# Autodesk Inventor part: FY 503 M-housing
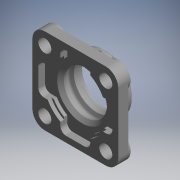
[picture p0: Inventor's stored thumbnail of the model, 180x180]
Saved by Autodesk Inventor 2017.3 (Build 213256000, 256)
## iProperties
Part Number: FY 503 M-housing
Material: Generic
Catalog Web Link: www.cadenas.de
Description: ayf_001hc_hh_hy-housing-Square flanged housings for Y-bearings
Vendor: SKF
Document SubType Name: Modeling
Designer: partserver
Manufacturer: SKF
Mass: 40.8035 g
Surface Area: 192.771 cm^2
Volume: 40.8035 cm^3
Density: 1 g/cm^3
Appearance: PSOLRGB-175-175-175
Category: PARTsolutions
Company: SKF
Title: FY 503 M-housing
Author: Cadenas PARTsolutions
Comments: Square flanged housings for Y-bearings
PSOL_IDENT_0: {$CADENAS_DATA\23d-libs\skf\bearings_units_and_housings\bearing_units\ball_bearing_units\y-units\y-b
PSOL_IDENT_1: earing_square_flanged_units_parts\ayf_001hc_hh_hy_housing.prj},196 {VTYP=3D},{NB=FY 503 M-housing},{
PSOL_IDENT_2: LINA=FY 503 M-housing},{NN=ayf_001hc_hh_hy-housing},{DATE=20.08.2020 13:45:19},{GEOMDATE=29.07.2020
PSOL_IDENT_3: 16:36:58},{VERSION=},{LINEID=8950},{WBVAR=COVER},{WBNUMERIC=}  {NB=FY 503 M-housing},{LINA=FY 503 M-
PSOL_IDENT_4: housing},{KT=DUMMY},{DESIGNATION=FY 503 M},{SS1=15.900},{T=32.900},{COVER=},{GN=1/4-28 SAE-LT},{D=40
PSOL_IDENT_5: .000},{DA=55.600},{DB1=50.000},{DB2=53.000},{DB=0.000},{A=26.000},{A1=11.000},{A2=17.000},{A3=3.200}
PSOL_IDENT_6: ,{A5=0.000},{J=54.000},{L=76.000},{N=11.500},{RG=1/4-28 UNF},{R1=19.000},{DN=6.500},{SWN=7.000},{J6=
PSOL_IDENT_7: 66.000},{J7=14.500},{N4=4.000},{EC=},{AEC=0.000},{DEC=0.000},{D1EC=0.000},{D2EC=0.000},{E=12},{DESIG
PSOL_IDENT_8: N=fy},{BRG=0.000},{ECPN=},{H4=MIN},{R2=MIN},{R3=MIN},{R4=MIN},{L1=MIN},{H5=MIN},{R5=MIN},{H6=MIN},{L
PSOL_IDENT_9: 2=MIN},{H7=MIN},{H8=MIN},{H9=MIN},{L3=MIN},{L4=MIN},{H10=MIN},{H11=MIN},{H12=MIN},{H13=MIN},{H14=MIN
PSOL_IDENT_10: },{R6=MIN},{L5=MIN},{H15=MIN},{H16=MIN},{SC=MIN}
NB: FY 503 M-housing
NN: ayf_001hc_hh_hy-housing
NT: Square flanged housings for Y-bearings
NBSYN: $DESIGNATION.$ECPN.-housing
LINA: FY 503 M-housing
CATALOG: SKF
DESIGNATION: FY 503 M
SS1: 15.9
T: 32.9
COVER: No End Cover
GN: 1/4-28 SAE-LT
D: 40
DA: 55.6
DB1: 50
DB2: 53
DB: 0
A: 26
A1: 11
A2: 17
A3: 3.2
A5: 0
J: 54
L: 76
N: 11.5
RG: 1/4-28 UNF
R1: 19
DN: 6.5
SWN: 7
J6: 66
J7: 14.5
N4: 4
AEC: 0
DEC: 0
D1EC: 0
D2EC: 0
DESIGN: fy
H4: 0
R2: 0
R3: 0
R4: 0
L1: 0
H5: 0
R5: 0
H6: 0
L2: 0
H7: 0
H8: 0
H9: 0
L3: 0
L4: 0
H10: 0
H11: 0
H12: 0
H13: 0
H14: 0
R6: 0
L5: 0
H15: 0
H16: 0
SC: 0
SUPPLIER: SKF
ARTICLENO: FY 503 M-housing
BOMINFO: FY 503 M-housing
CREATOR: CADENAS GmbH
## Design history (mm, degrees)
sketch "Sketch_1"
  geometry: L1 (0, 0)-(0, 26); L2 (19.079, 11)-(19.079, 9); L3 (19.079, 9)-(22.079, 6); L4 (22.079, 6)-(25.941, 6); L5 (25.941, 6)-(25.941, 3.2); L6 (25.941, 3.2)-(27.8, 3.2); L7 (27.8, 3.2)-(27.8, 0); L8 (27.8, 0)-(53.74, 0); L9 (53.74, 0)-(53.74, 9); L10 (53.74, 9)-(29.5, 9); L11 (26.521, 11.65)-(24.99, 24.675); L12 (23.5, 26)-(20, 26); L13 (20, 26)-(20, 23.921); L14 (20, 23.921)-(19.079, 23); A1 r 20 centre (0, 17) between (19.079, 11) and (19.079, 23); A2 r 3 centre (29.5, 12) between (26.521, 11.65) and (29.5, 9); A3 r 1.5 centre (23.5, 24.5) between (24.99, 24.675) and (23.5, 26)
  constraints: 28 end point, 6 point on circle, 3 centre point
revolve "Revolution1" sketch "Sketch_1" stored, may be unused: angle "d0" = 360 deg
sketch "Sketch_2"
  geometry: L1 (-19.222, -34.778)-(-9.27, -24.826); L2 (9.27, -24.826)-(19.222, -34.778); L3 (34.778, -19.222)-(24.826, -9.27); L4 (24.826, 9.27)-(34.778, 19.222); L5 (19.222, 34.778)-(9.27, 24.826); L6 (-9.27, 24.826)-(-19.222, 34.778); L7 (-34.778, 19.222)-(-24.826, 9.27); L8 (-24.826, -9.27)-(-34.778, -19.222); C1 r 26 at (0, 0); A1 r 11 centre (-27, -27) between (-34.778, -19.222) and (-19.222, -34.778); A2 r 26.5 centre (0, 0) between (-9.27, -24.826) and (9.27, -24.826); A3 r 11 centre (27, -27) between (19.222, -34.778) and (34.778, -19.222); A4 r 26.5 centre (0, 0) between (24.826, -9.27) and (24.826, 9.27); A5 r 11 centre (27, 27) between (34.778, 19.222) and (19.222, 34.778); A6 r 26.5 centre (0, 0) between (9.27, 24.826) and (-9.27, 24.826); A7 r 11 centre (-27, 27) between (-19.222, 34.778) and (-34.778, 19.222); A8 r 26.5 centre (0, 0) between (-24.826, 9.27) and (-24.826, -9.27); 1 further point
  constraints: 16 end point, 16 point on circle, 9 centre point
extrude "Extrusion1" join sketch "Sketch_2" distance "d1" = 2; taper "d2" = 0 deg
sketch "Sketch_3"
  geometry: L1 (76, -76)-(76, 76); L2 (76, 76)-(-76, 76); L3 (-76, 76)-(-76, -76); L4 (-76, -76)-(76, -76); L5 (27, 38)-(-27, 38); L6 (-38, 27)-(-38, -27); L7 (-27, -38)-(27, -38); L8 (38, -27)-(38, 27); A1 r 11 centre (27, 27) between (38, 27) and (27, 38); A2 r 11 centre (-27, 27) between (-27, 38) and (-38, 27); A3 r 11 centre (-27, -27) between (-38, -27) and (-27, -38); A4 r 11 centre (27, -27) between (27, -38) and (38, -27)
  constraints: 16 end point, 8 point on circle, 4 centre point
extrude "Extrusion2" cut sketch "Sketch_3" distance "d3" = 26; taper "d4" = 0 deg
sketch "Sketch4"
  geometry: 1 further point
hole "Hole1" sketch "Sketch4" at (0, 65) diameter "d5" = 11.5; stored, may be unused: countersink angle "d9" = 90 deg, drill point angle "d11" = 0 deg; dims "d6" = 6, "d7" = 4, "d8" = 2, "d10" = 11
pattern_linear "Rectangular Pattern1" dims "d14" = 54, "d17" = 54
sketch "Sketch_8"
  geometry: L1 (19, -25.657)-(16.666, -5.793); L2 (16.666, -5.793)-(19.819, -5.423); L3 (19.819, -5.423)-(22.153, -25.286); L4 (22.153, -25.286)-(19, -25.657); L5 (19, -25.657)-(16.666, -5.793)
  constraints: 10 end point
revolve "Revolution2" sketch "Sketch_8" stored, may be unused: angle "d18" = 360 deg
sketch "Sketch_6"
  geometry: L1 (-50, -14.5)-(50, -14.5); L2 (-35, -14.5)-(-31, -14.5); A1 r 2 centre (-33, -14.5) between (-35, -14.5) and (-31, -14.5)
  constraints: 4 end point, 2 point on circle, 1 centre point
revolve "Revolution3" sketch "Sketch_6" stored, may be unused: angle "d19" = 360 deg
sketch "Sketch_10"
  geometry: L1 (0, 3)-(0, 29); L2 (16, 21.043)-(16, 9.496); L3 (16, 9.496)-(22.25, 13.104); L4 (22.25, 17.434)-(16, 21.043); A1 r 2.5 centre (21, 15.269) between (22.25, 13.104) and (22.25, 17.434)
  constraints: 8 end point, 2 point on circle, 1 centre point
revolve "Revolution4" sketch "Sketch_10" stored, may be unused: angle "d20" = 360 deg
sketch "Sketch_7"
  geometry: L1 (-17.202, -10.203)-(17.202, -10.203); L2 (17.202, 10.203)-(-17.202, 10.203); A1 r 20 centre (0, 0) between (-17.202, 10.203) and (-17.202, -10.203); A2 r 20 centre (0, 0) between (17.202, -10.203) and (17.202, 10.203)
  constraints: 4 end point, 4 point on circle, 2 centre point
extrude "Extrusion3" cut sketch "Sketch_7" distance "d21" = 11.18; taper "d22" = 0 deg
sketch "Sketch_11"
  geometry: L1 (27.75, 13.2)-(13.2, 13.2); L2 (13.2, 13.2)-(13.2, 27.75); L3 (8.2, 32.75)-(-8.2, 32.75); L4 (-13.2, 27.75)-(-13.2, 13.2); L5 (-13.2, 13.2)-(-27.75, 13.2); L6 (-32.75, 8.2)-(-32.75, -8.2); L7 (-27.75, -13.2)-(-13.2, -13.2); L8 (-13.2, -13.2)-(-13.2, -27.75); L9 (-8.2, -32.75)-(8.2, -32.75); L10 (13.2, -27.75)-(13.2, -13.2); L11 (13.2, -13.2)-(27.75, -13.2); L12 (32.75, -8.2)-(32.75, 8.2); A1 r 5 centre (27.75, 8.2) between (32.75, 8.2) and (27.75, 13.2); A2 r 5 centre (8.2, 27.75) between (13.2, 27.75) and (8.2, 32.75); A3 r 5 centre (-8.2, 27.75) between (-8.2, 32.75) and (-13.2, 27.75); A4 r 5 centre (-27.75, 8.2) between (-27.75, 13.2) and (-32.75, 8.2); A5 r 5 centre (-27.75, -8.2) between (-32.75, -8.2) and (-27.75, -13.2); A6 r 5 centre (-8.2, -27.75) between (-13.2, -27.75) and (-8.2, -32.75); A7 r 5 centre (8.2, -27.75) between (8.2, -32.75) and (13.2, -27.75); A8 r 5 centre (27.75, -8.2) between (27.75, -13.2) and (32.75, -8.2)
  constraints: 24 end point, 16 point on circle, 8 centre point
extrude "Extrusion4" cut sketch "Sketch_11" distance "d23" = 6; taper "d24" = 0 deg
sketch "Sketch_12"
  geometry: L1 (-36.297, 3.807)-(-34.964, 3.807); L2 (-34.821, 3.866)-(-34.766, 3.921); L3 (-34.552, 4.01)-(-33.546, 4.01); L4 (-33.403, 3.95)-(-33.319, 3.866); L5 (-33.176, 3.807)-(-32.045, 3.807); L6 (-32.045, 3.807)-(-32.045, 3.179); L7 (-32.045, 3.179)-(-33.26, 3.179); L8 (-33.462, 2.977)-(-33.462, 1.634); L9 (-33.511, 1.502)-(-34.678, 0.142); L10 (-34.678, 0.142)-(-35.226, 0.69); L11 (-35.285, 0.833)-(-35.285, 2.369); L12 (-35.487, 2.572)-(-36.297, 2.572); L13 (-36.5, 2.369)-(-36.5, 0.638); L14 (-36.432, 0.486)-(-34.678, -1.073); L15 (-34.678, -1.073)-(-36.297, -1.073); L16 (-36.5, -1.276)-(-36.5, -2.896); L17 (-36.297, -3.098)-(-34.964, -3.098); L18 (-34.821, -3.039)-(-34.737, -2.955); L19 (-34.594, -2.896)-(-33.749, -2.896); L20 (-33.606, -2.955)-(-33.522, -3.039); L21 (-33.379, -3.098)-(-32.045, -3.098); L22 (-32.045, -3.098)-(-32.045, -3.503); L23 (-32.045, -3.503)-(-34.475, -3.503); L24 (-34.678, -3.706)-(-34.678, -6.946); L25 (-34.88, -7.148)-(-35.69, -7.148); L26 (-35.892, -6.946)-(-35.892, -6.136); L27 (-35.69, -5.933)-(-35.487, -5.933); L28 (-35.285, -5.731)-(-35.285, -4.313); L29 (-35.487, -4.111)-(-36.227, -4.111); L30 (-36.5, -4.383)-(-36.5, -8.718); L31 (-36.248, -8.971)-(-34.273, -8.971); L32 (-34.07, -8.768)-(-34.07, -5.528); L33 (-33.867, -5.326)-(-32.45, -5.326); L34 (-32.248, -5.528)-(-32.248, -7.553); L35 (-32.45, -7.756)-(-33.26, -7.756); L36 (-33.462, -7.958)-(-33.462, -9.376); L37 (-33.26, -9.578)-(-31.843, -9.578); L38 (-31.64, -9.376)-(-31.64, -3.706); L39 (-31.843, -3.503)-(-31.843, -3.098); L40 (-31.64, -2.896)-(-31.64, -1.276); L41 (-31.843, -1.073)-(-33.462, -1.073); L42 (-33.462, -1.073)-(-31.699, 0.69); L43 (-31.64, 0.833)-(-31.64, 2.977); L44 (-31.843, 3.179)-(-31.843, 3.807); L45 (-31.64, 4.01)-(-31.64, 5.63); L46 (-31.843, 5.832)-(-33.26, 5.832); L47 (-33.665, 5.427)-(-33.867, 5.427); L48 (-34.07, 5.63)-(-34.07, 6.356); L49 (-34.011, 6.499)-(-33.927, 6.583); L50 (-33.867, 6.726)-(-33.867, 8.059); L51 (-34.07, 8.262)-(-34.678, 8.262); L52 (-34.88, 8.059)-(-34.88, 6.726); L53 (-34.821, 6.583)-(-34.737, 6.499); L54 (-34.678, 6.356)-(-34.678, 5.63); L55 (-34.88, 5.427)-(-35.59, 5.427); L56 (-35.892, 5.729)-(-35.892, 7.452); L57 (-35.69, 7.654)-(-35.487, 7.654); L58 (-35.285, 7.857)-(-35.285, 9.882); L59 (-35.487, 10.085)-(-36.297, 10.085); L60 (-36.5, 9.882)-(-36.5, 4.01); A1 r 0.203 centre (-36.297, 4.01) between (-36.5, 4.01) and (-36.297, 3.807); A2 r 0.203 centre (-34.964, 4.01) between (-34.964, 3.807) and (-34.821, 3.866); A3 r 0.302 centre (-34.552, 3.707) between (-34.552, 4.01) and (-34.766, 3.921); A4 r 0.203 centre (-33.546, 3.807) between (-33.403, 3.95) and (-33.546, 4.01); A5 r 0.203 centre (-33.176, 4.01) between (-33.319, 3.866) and (-33.176, 3.807); A6 r 0.203 centre (-33.26, 2.977) between (-33.26, 3.179) and (-33.462, 2.977); A7 r 0.203 centre (-33.665, 1.634) between (-33.511, 1.502) and (-33.462, 1.634); A8 r 0.202 centre (-35.083, 0.833) between (-35.285, 0.833) and (-35.226, 0.69); A9 r 0.203 centre (-35.488, 2.369) between (-35.285, 2.369) and (-35.487, 2.572); A10 r 0.203 centre (-36.297, 2.369) between (-36.297, 2.572) and (-36.5, 2.369); A11 r 0.203 centre (-36.297, 0.638) between (-36.5, 0.638) and (-36.432, 0.486); A12 r 0.203 centre (-36.297, -1.276) between (-36.297, -1.073) and (-36.5, -1.276); A13 r 0.203 centre (-36.297, -2.896) between (-36.5, -2.896) and (-36.297, -3.098); A14 r 0.203 centre (-34.964, -2.896) between (-34.964, -3.098) and (-34.821, -3.039); A15 r 0.203 centre (-34.594, -3.098) between (-34.594, -2.896) and (-34.737, -2.955); A16 r 0.203 centre (-33.749, -3.098) between (-33.606, -2.955) and (-33.749, -2.896); A17 r 0.203 centre (-33.379, -2.896) between (-33.522, -3.039) and (-33.379, -3.098); A18 r 0.203 centre (-34.475, -3.706) between (-34.475, -3.503) and (-34.678, -3.706); A19 r 0.203 centre (-34.88, -6.946) between (-34.88, -7.148) and (-34.678, -6.946); A20 r 0.203 centre (-35.69, -6.946) between (-35.892, -6.946) and (-35.69, -7.148); A21 r 0.203 centre (-35.69, -6.136) between (-35.69, -5.933) and (-35.892, -6.136); A22 r 0.203 centre (-35.488, -5.731) between (-35.487, -5.933) and (-35.285, -5.731); A23 r 0.203 centre (-35.488, -4.313) between (-35.285, -4.313) and (-35.487, -4.111); A24 r 0.273 centre (-36.227, -4.383) between (-36.227, -4.111) and (-36.5, -4.383); A25 r 0.252 centre (-36.248, -8.718) between (-36.5, -8.718) and (-36.248, -8.971); A26 r 0.203 centre (-34.273, -8.768) between (-34.273, -8.971) and (-34.07, -8.768); A27 r 0.203 centre (-33.867, -5.528) between (-33.867, -5.326) and (-34.07, -5.528); A28 r 0.203 centre (-32.45, -5.528) between (-32.248, -5.528) and (-32.45, -5.326); A29 r 0.203 centre (-32.45, -7.553) between (-32.45, -7.756) and (-32.248, -7.553); A30 r 0.203 centre (-33.26, -7.958) between (-33.26, -7.756) and (-33.462, -7.958); A31 r 0.203 centre (-33.26, -9.376) between (-33.462, -9.376) and (-33.26, -9.578); A32 r 0.203 centre (-31.843, -9.376) between (-31.843, -9.578) and (-31.64, -9.376); A33 r 0.203 centre (-31.843, -3.706) between (-31.64, -3.706) and (-31.843, -3.503); A34 r 0.203 centre (-31.843, -2.896) between (-31.843, -3.098) and (-31.64, -2.896); A35 r 0.203 centre (-31.843, -1.276) between (-31.64, -1.276) and (-31.843, -1.073); A36 r 0.202 centre (-31.842, 0.833) between (-31.699, 0.69) and (-31.64, 0.833); A37 r 0.203 centre (-31.843, 2.977) between (-31.64, 2.977) and (-31.843, 3.179); A38 r 0.203 centre (-31.843, 4.01) between (-31.843, 3.807) and (-31.64, 4.01); A39 r 0.203 centre (-31.843, 5.629) between (-31.64, 5.63) and (-31.843, 5.832); A40 r 0.203 centre (-33.26, 5.629) between (-33.26, 5.832) and (-33.462, 5.63); A41 r 0.203 centre (-33.665, 5.63) between (-33.665, 5.427) and (-33.462, 5.63); A42 r 0.203 centre (-33.867, 5.63) between (-34.07, 5.63) and (-33.867, 5.427); A43 r 0.202 centre (-33.868, 6.356) between (-34.011, 6.499) and (-34.07, 6.356); A44 r 0.202 centre (-34.07, 6.726) between (-33.927, 6.583) and (-33.867, 6.726); A45 r 0.203 centre (-34.07, 8.059) between (-33.867, 8.059) and (-34.07, 8.262); A46 r 0.203 centre (-34.677, 8.059) between (-34.678, 8.262) and (-34.88, 8.059); A47 r 0.202 centre (-34.678, 6.726) between (-34.88, 6.726) and (-34.821, 6.583); A48 r 0.202 centre (-34.88, 6.356) between (-34.678, 6.356) and (-34.737, 6.499); A49 r 0.203 centre (-34.88, 5.63) between (-34.88, 5.427) and (-34.678, 5.63); A50 r 0.302 centre (-35.59, 5.729) between (-35.892, 5.729) and (-35.59, 5.427); A51 r 0.203 centre (-35.69, 7.452) between (-35.69, 7.654) and (-35.892, 7.452); A52 r 0.203 centre (-35.488, 7.857) between (-35.487, 7.654) and (-35.285, 7.857); A53 r 0.203 centre (-35.488, 9.882) between (-35.285, 9.882) and (-35.487, 10.085); A54 r 0.203 centre (-36.297, 9.882) between (-36.297, 10.085) and (-36.5, 9.882)
  constraints: 120 end point, 108 point on circle, 54 centre point
extrude "Extrusion5" join sketch "Sketch_12" distance "d25" = 0.7; taper "d26" = 0 deg
node "brg_XY"
node "brg_YZ"
node "brg_ZX"
node "brg_X"
node "brg_Y"
node "brg_Z"
node "brg_Center"
node "gn_XY"
node "gn_YZ"
node "gn_ZX"
node "gn_X"
node "gn_Y"
node "gn_Z"
node "gn_Center"
node "housing_XY"
node "housing_YZ"
node "housing_ZX"
node "housing_X"
node "housing_Y"
node "housing_Z"
node "housing_Center"
body "Solid1"
other parameters: "d27" = 0
